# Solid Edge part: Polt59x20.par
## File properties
Author: Türk
Template: Iso Part.par
Last saved by: Türk
Revision: 11
Application: Solid Edge
Accuracy: 0,990
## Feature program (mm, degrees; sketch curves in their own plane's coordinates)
thread "unnamed Thread 1"
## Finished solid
Body 1: solid body, 23 faces, 45 edges, 24 vertices.
  Faces by surface: plane 21, cylinder 2
  Edges by curve: line 42, circle 3
Bounding box of the edges (mm): 24.000 x 69.500 x 27.713, from (-12, -10, -13.8564) to (12, 59.5, 13.8564).
Cylindrical faces by radius (mm): R10 x2
Planar faces by outward normal: +x 1, +y 2, -x 1, -y 1, oblique 16
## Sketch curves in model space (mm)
circle centre (0, 0, 0) radius 13.8564
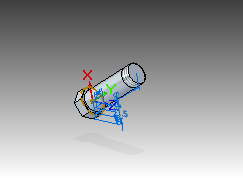
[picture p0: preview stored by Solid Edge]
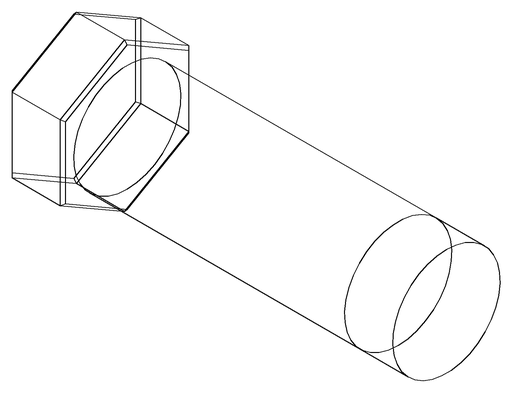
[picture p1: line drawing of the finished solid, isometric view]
